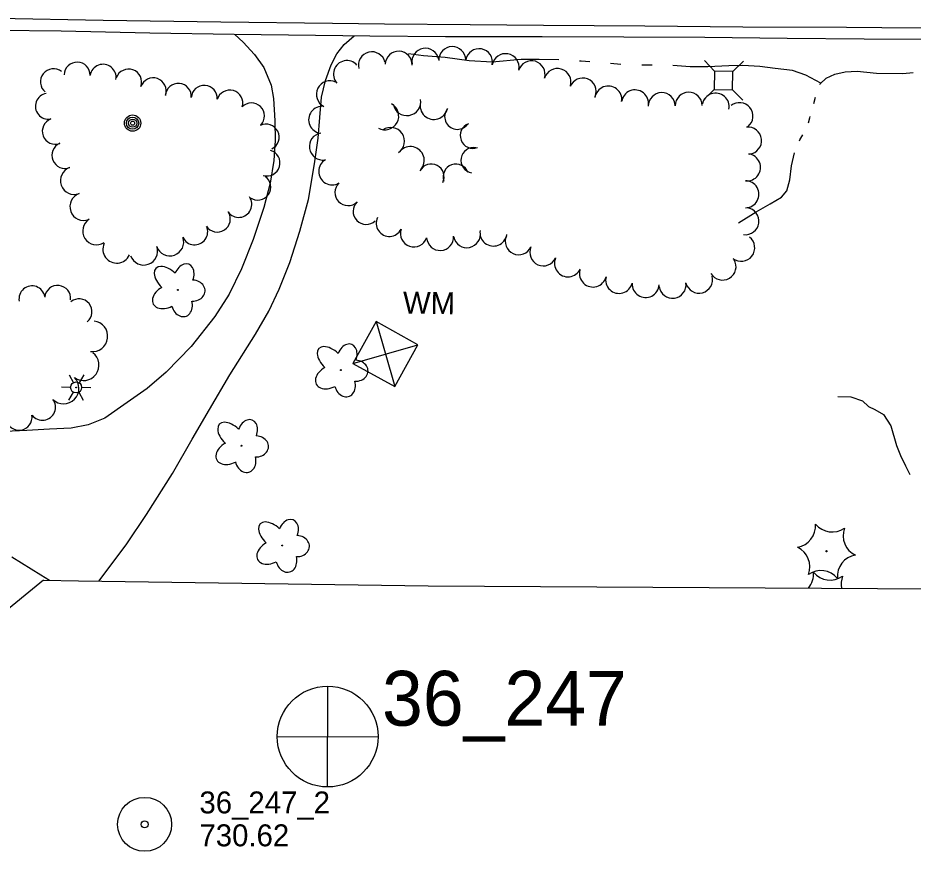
# Model space of a CAD drawing. Extents: x 589250 to 1188077, y 162953 to 363065.
# Drawn here: x 595184.3 to 595429, y 164804.2 to 165039.5 of the extents above; entities that cross this region are included whole.
import ezdxf

# ---------------------------------------------------------------- set-up
doc = ezdxf.new("R2010")
doc.units = 0
for name, color, linetype in [('E_DWY', 7, 'Continuous'), ('E_LAND_TreeLine_P', 7, 'Continuous'), ('E_LAND_Vegetation', 7, 'Continuous'), ('E_LTG', 7, 'Continuous'), ('E_MAP_Limits', 7, 'Continuous'), ('E_MAP_PassPoints', 7, 'Continuous'), ('E_MAP_PhotoCenter', 7, 'Continuous'), ('E_MISCPROP', 7, 'Continuous'), ('E_MISCPROP_Text', 7, 'Continuous'), ('E_RDWY', 7, 'Continuous'), ('E_RDWY_Gravel', 7, 'Continuous'), ('E_UTL_AG_Bold', 7, 'Continuous'), ('E_WTR_FlowLine', 7, 'Continuous')]:
    doc.layers.add(name, color=color, linetype=linetype)

msp = doc.modelspace()

# ---------------------------------------------------------------- linework, layer by layer
at = {"layer": 'E_DWY'}
for p, q in [((595243.55, 165034.97), (595245.91, 165032.85)), ((595273.48, 165032.24), (595276.24, 165034.58)), ((595245.91, 165032.85), (595248.96, 165029.47)), ((595271.46, 165029.69), (595273.48, 165032.24)), ((595248.96, 165029.47), (595251.49, 165025.92)), ((595269.9, 165026.66), (595271.46, 165029.69)), ((595268.35, 165022.42), (595269.9, 165026.66)), ((595251.49, 165025.92), (595253.49, 165021.14)), ((595267.32, 165017.84), (595268.35, 165022.42)), ((595253.49, 165021.14), (595254.14, 165017.47)), ((595254.14, 165017.47), (595254.48, 165011.4)), ((595266.82, 165012.31), (595267.32, 165017.84)), ((595266.37, 165006.61), (595266.82, 165012.31)), ((595254.48, 165011.4), (595254.61, 165005.98)), ((595265.41, 164999.58), (595266.37, 165006.61)), ((595254.61, 165005.98), (595254.26, 165000.53)), ((595254.26, 165000.53), (595253.22, 164994.31)), ((595263.71, 164989.87), (595265.41, 164999.58)), ((595253.22, 164994.31), (595251.5, 164987.65)), ((595261.38, 164981.19), (595263.71, 164989.87)), ((595251.5, 164987.65), (595248.57, 164978.86)), ((595258.66, 164972.59), (595261.38, 164981.19)), ((595248.57, 164978.86), (595245.38, 164970.86)), ((595255.72, 164965.32), (595258.66, 164972.59)), ((595245.38, 164970.86), (595242.08, 164963.92)), ((595252.85, 164959.25), (595255.72, 164965.32)), ((595242.08, 164963.92), (595238.12, 164957.87)), ((595238.12, 164957.87), (595231.65, 164949.65)), ((595249.24, 164953.02), (595252.85, 164959.25)), ((595242.22, 164941.88), (595249.24, 164953.02)), ((595231.65, 164949.65), (595224.78, 164942.6)), ((595224.78, 164942.6), (595219.58, 164938.18)), ((595236.62, 164932.42), (595242.22, 164941.88)), ((595219.58, 164938.18), (595214.11, 164934.29)), ((595214.11, 164934.29), (595208.04, 164930.06)), ((595231.91, 164924.26), (595236.62, 164932.42)), ((595208.04, 164930.06), (595203.47, 164928.22)), ((595186.73, 164926.61), (595176.03, 164926.17)), ((595192.91, 164926.98), (595186.73, 164926.61)), ((595198.8, 164927.26), (595192.91, 164926.98)), ((595203.47, 164928.22), (595198.8, 164927.26)), ((595226.51, 164914.91), (595231.91, 164924.26)), ((595219.42, 164903.69), (595226.51, 164914.91)), ((595214.06, 164895.62), (595219.42, 164903.69)), ((595206.5, 164885.48), (595214.06, 164895.62)), ((595182.63, 164892.06), (595190.56, 164887.17)), ((595190.56, 164887.17), (595192.95, 164885.7))]:
    msp.add_line(p, q, dxfattribs=at)
at = {"layer": 'E_LAND_TreeLine_P'}
for centre, radius, start, end in [((595295.69, 165027.53), 3.69, 9.7406, 189.7406), ((595303.04, 165027.98), 3.69, 1.1157, 181.1157), ((595281.05, 165026.55), 3.69, 13.4116, 193.4116), ((595288.39, 165026.7), 3.69, 358.0637, 178.0637), ((595310.36, 165027.38), 3.69, 349.5869, 169.5869), ((595317.61, 165026.04), 3.69, 349.5869, 169.5869), ((595200.48, 165023.85), 3.56, 358.3115, 178.3115), ((595207.56, 165023.27), 3.56, 350.8386, 170.8386), ((595274.24, 165024.14), 3.69, 41.8847, 221.8847), ((595324.72, 165024.1), 3.69, 343.3792, 163.3792), ((595193.99, 165022.04), 3.56, 51.426, 231.426), ((595214.54, 165021.95), 3.56, 340.4339, 160.4339), ((595331.8, 165021.99), 3.69, 343.3792, 163.3792), ((595221.25, 165019.56), 3.56, 340.2375, 160.2375), ((595228.14, 165018.03), 3.56, 355.3287, 175.3287), ((595269.56, 165018.6), 3.69, 63.4212, 243.4212), ((595338.69, 165019.37), 3.69, 338.5138, 158.5138), ((595192.62, 165015.36), 3.56, 99.7772, 279.7772), ((595235.24, 165017.5), 3.56, 356.6029, 176.6029), ((595242.2, 165016.22), 3.56, 343.8822, 163.8822), ((595345.7, 165017.19), 3.69, 351.7023, 171.7023), ((595353, 165016.13), 3.69, 351.7023, 171.7023), ((595360.32, 165015.38), 3.69, 0.8292, 180.8292), ((595367.7, 165015.49), 3.69, 0.8292, 180.8292), ((595375.04, 165015.26), 3.69, 348.7577, 168.7577), ((595290.63, 165016.57), 3.78, 189.8793, 9.8793), ((595248.13, 165012.68), 3.56, 316.0681, 136.0681), ((595267.46, 165011.64), 3.69, 83.4005, 263.4005), ((595284.62, 165012.66), 3.78, 241.6772, 61.6772), ((595298.02, 165015.53), 3.78, 167.0923, 347.0923), ((595304.44, 165012.52), 3.49, 141.5636, 321.5636), ((595381.58, 165012.65), 3.69, 309.0768, 129.0768), ((595194.51, 165008.53), 3.56, 110.6636, 290.6636), ((595252.14, 165006.91), 3.56, 296.6672, 116.6672), ((595286.18, 165005.77), 3.78, 304.4135, 124.4135), ((595308.7, 165007.31), 3.49, 110.7702, 290.7702), ((595383.92, 165005.95), 3.69, 276.6589, 96.6589), ((595267.66, 165004.33), 3.69, 99.0327, 279.0327), ((595197.12, 165001.91), 3.56, 112.2184, 292.2184), ((595291.61, 165000.54), 3.78, 317.9949, 137.9949), ((595252.37, 164999.83), 3.56, 253.8297, 73.8297), ((595308.9, 165000.57), 3.49, 80.0281, 260.0281), ((595383.64, 164998.62), 3.69, 263.292, 83.292), ((595270.2, 164997.54), 3.69, 120.2629, 300.2629), ((595297.31, 164996.06), 3.49, 332.8197, 152.8197), ((595304.04, 164996.03), 3.49, 19.5506, 199.5506), ((595199.68, 164995.02), 3.79, 110.0985, 290.0985), ((595249.85, 164993.25), 3.56, 234.9615, 54.9615), ((595383.21, 164991.27), 3.69, 270.417, 90.417), ((595274.54, 164991.77), 3.58, 133.8249, 313.8249), ((595202.29, 164987.9), 3.79, 110.0985, 290.0985), ((595244.67, 164988.51), 3.56, 215.3288, 35.3288), ((595279.49, 164986.61), 3.58, 133.8249, 313.8249), ((595383.2, 164983.9), 3.69, 262.1707, 82.1707), ((595238.79, 164984.5), 3.56, 212.8084, 32.8084), ((595285.83, 164983.32), 3.58, 153.5837, 333.5837), ((595205.79, 164981.23), 3.79, 122.4705, 302.4705), ((595232.61, 164980.99), 3.56, 204.821, 24.821), ((595292.54, 164980.55), 3.69, 161.4466, 341.4466), ((595299.72, 164979.59), 3.69, 183.2441, 3.2441), ((595307.04, 164980.34), 3.69, 191.7269, 11.7269), ((595314.29, 164980.79), 3.69, 171.3267, 351.3267), ((595321.2, 164978.4), 3.69, 155.3334, 335.3334), ((595211.31, 164976.22), 3.79, 155.7934, 335.7934), ((595225.82, 164978.21), 3.79, 199.3254, 19.3254), ((595382.06, 164976.64), 3.69, 232.1268, 52.1268), ((595218.67, 164975.7), 3.79, 199.3254, 19.3254), ((595327.93, 164975.37), 3.69, 155.8498, 335.8498), ((595334.67, 164972.37), 3.69, 156.0176, 336.0176), ((595376.94, 164971.49), 3.69, 210.3307, 30.3307), ((595341.49, 164969.59), 3.69, 166.2594, 346.2594), ((595348.66, 164967.84), 3.69, 166.2594, 346.2594), ((595370.51, 164967.91), 3.69, 194.8378, 14.8378), ((595188.12, 164962.66), 3.55, 10, 190), ((595195.14, 164962.79), 3.55, 353.9177, 173.9177), ((595355.92, 164966.72), 3.69, 176.5602, 356.5602), ((595363.28, 164966.52), 3.69, 187.542, 7.542), ((595200.99, 164959.12), 3.55, 309.3285, 129.3285), ((595204.62, 164952.41), 4.21, 263.0906, 83.0906), ((595202.24, 164944.52), 4.21, 233.7609, 53.7609), ((595196.76, 164938.16), 4.21, 225.416, 45.416), ((595190.99, 164933.01), 3.55, 217.5212, 37.5212), ((595184.59, 164930.28), 3.55, 188.7829, 8.7829)]:
    msp.add_arc(centre, radius, start, end, dxfattribs=at)
at = {"layer": 'E_LAND_Vegetation'}
for centre, radius in [((595228.02, 164965.09), 0.128), ((595272.58, 164943.17), 0.128), ((595245.37, 164922.47), 0.128), ((595256.55, 164895.19), 0.128), ((595405.37, 164893.61), 0.167)]:
    msp.add_circle(centre, radius, dxfattribs=at)
for centre, radius, start, end in [((595396.46, 164900.54), 5.91, 279.2862, 4.9623), ((595406.91, 164904.78), 5.9, 219.2465, 305.0114), ((595415.81, 164897.86), 5.9, 159.2465, 245.0114), ((595394.92, 164889.36), 5.9, 339.2465, 65.0114), ((595414.23, 164886.74), 5.9, 99.2418, 185.0068), ((595403.82, 164882.44), 5.9, 39.2465, 125.0114), ((595395.91, 164887.35), 5.91, 320.1017, 4.9623), ((595406.37, 164891.6), 5.9, 219.2465, 305.0114), ((595415.27, 164884.67), 5.9, 159.2465, 191.3555)]:
    msp.add_arc(centre, radius, start, end, dxfattribs=at)
for centre, major_axis, ratio in [((595229.69, 164968.74), (-1.32, -3.38), 0.716896), ((595225.45, 164967.73), (3.45, -3.27), 0.560249), ((595232, 164964.92), (-3.45, 0.14), 0.832022), ((595225.02, 164963.23), (3.72, 1.99), 0.691916), ((595229.13, 164961.35), (-0.89, 3.5), 0.782863), ((595274.26, 164946.81), (-1.32, -3.38), 0.716896), ((595270.02, 164945.8), (3.45, -3.27), 0.560249), ((595276.56, 164942.99), (-3.45, 0.14), 0.832022), ((595269.58, 164941.3), (3.72, 1.99), 0.691916), ((595273.7, 164939.42), (-0.89, 3.5), 0.782863), ((595242.8, 164925.11), (3.45, -3.27), 0.560249), ((595247.05, 164926.11), (-1.32, -3.38), 0.716896), ((595249.35, 164922.29), (-3.45, 0.14), 0.832022), ((595242.37, 164920.6), (3.72, 1.99), 0.691916), ((595246.49, 164918.73), (-0.89, 3.5), 0.782863), ((595253.99, 164897.82), (3.45, -3.27), 0.560249), ((595258.23, 164898.83), (-1.32, -3.38), 0.716896), ((595260.53, 164895.01), (-3.45, 0.14), 0.832022), ((595253.55, 164893.32), (3.72, 1.99), 0.691916), ((595257.67, 164891.44), (-0.89, 3.5), 0.782863)]:
    msp.add_ellipse(centre, major_axis=major_axis, ratio=ratio, start_param=1.570796, end_param=4.712389, dxfattribs=at)
at = {"layer": 'E_LTG'}
for p, q in [((595198.26, 164941.91), (595199.48, 164939.73)), ((595202.26, 164941.85), (595200.98, 164939.7)), ((595198.7, 164938.44), (595196.2, 164938.48)), ((595204.2, 164938.35), (595201.7, 164938.39)), ((595199.43, 164937.13), (595198.15, 164934.99)), ((595200.93, 164937.1), (595202.14, 164934.92))]:
    msp.add_line(p, q, dxfattribs=at)
for radius in [1.5, 0.125]:
    msp.add_circle((595200.2, 164938.42), radius, dxfattribs=at)
at = {"layer": 'E_MAP_Limits'}
for p, q in [((595191.23, 164885.74), (595092.3, 164804.2)), ((595191.23, 164885.74), (595200.81, 164885.56)), ((595200.81, 164885.56), (595296.48, 164884.2)), ((595296.48, 164884.2), (595479.15, 164883.09))]:
    msp.add_line(p, q, dxfattribs=at)
at = {"layer": 'E_MAP_PassPoints'}
for radius in [7.38, 7.38, 0.945, 0.945]:
    msp.add_circle((595218.91, 164818.91), radius, dxfattribs=at)
at = {"layer": 'E_MAP_PhotoCenter'}
for p, q in [((595268.92, 164856.71), (595268.86, 164829.3)), ((595268.92, 164856.71), (595268.86, 164829.3)), ((595255.23, 164842.91), (595282.69, 164842.89)), ((595255.23, 164842.91), (595282.69, 164842.89))]:
    msp.add_line(p, q, dxfattribs=at)
msp.add_circle((595268.97, 164842.91), 13.78, dxfattribs=at)
msp.add_circle((595268.97, 164842.91), 13.78, dxfattribs=at)
at = {"layer": 'E_MISCPROP'}
for p, q in [((595282.21, 164956.45), (595275.89, 164944.99)), ((595282.21, 164956.45), (595287.34, 164938.67)), ((595293.67, 164950.12), (595282.21, 164956.45)), ((595275.89, 164944.99), (595293.67, 164950.12)), ((595287.34, 164938.67), (595293.67, 164950.12)), ((595275.89, 164944.99), (595287.34, 164938.67))]:
    msp.add_line(p, q, dxfattribs=at)
for radius in [2.23, 1.67, 1.12, 0.558]:
    msp.add_circle((595215.64, 165010.73), radius, dxfattribs=at)
at = {"layer": 'E_RDWY'}
for p, q in [((595174.81, 165039.52), (595207.61, 165038.94)), ((595207.61, 165038.94), (595239.72, 165038.47)), ((595239.72, 165038.47), (595270.32, 165038.09)), ((595270.32, 165038.09), (595284.53, 165037.92)), ((595284.53, 165037.92), (595307.91, 165037.68)), ((595307.91, 165037.68), (595327.98, 165037.53)), ((595327.98, 165037.53), (595355.71, 165037.35)), ((595355.71, 165037.35), (595382.49, 165037.11)), ((595382.49, 165037.11), (595410.79, 165036.96)), ((595410.79, 165036.96), (595420.49, 165036.87)), ((595420.49, 165036.87), (595448.68, 165036.74))]:
    msp.add_line(p, q, dxfattribs=at)
at = {"layer": 'E_RDWY_Gravel'}
for p, q in [((595196.08, 165035.91), (595171.59, 165036.19)), ((595220.32, 165035.32), (595196.08, 165035.91)), ((595243.37, 165034.97), (595220.32, 165035.32)), ((595280.52, 165034.53), (595243.37, 165034.97)), ((595301.2, 165034.36), (595280.52, 165034.53)), ((595327.62, 165034.3), (595301.2, 165034.36)), ((595349.93, 165034.22), (595327.62, 165034.3)), ((595372.1, 165034.11), (595349.93, 165034.22)), ((595394.57, 165033.89), (595372.1, 165034.11)), ((595415.66, 165033.72), (595394.57, 165033.89)), ((595435.08, 165033.64), (595415.66, 165033.72))]:
    msp.add_line(p, q, dxfattribs=at)
at = {"layer": 'E_UTL_AG_Bold'}
for p, q in [((595374.77, 165024.96), (595371.99, 165027.84)), ((595379.77, 165024.88), (595382.64, 165027.66)), ((595374.77, 165024.96), (595374.69, 165019.96)), ((595379.77, 165024.88), (595374.77, 165024.96)), ((595379.68, 165019.88), (595379.77, 165024.88)), ((595374.69, 165019.96), (595371.81, 165017.18)), ((595374.69, 165019.96), (595379.68, 165019.88)), ((595379.68, 165019.88), (595382.47, 165017))]:
    msp.add_line(p, q, dxfattribs=at)
at = {"layer": 'E_WTR_FlowLine'}
for p, q in [((595295.17, 165029.11), (595291.03, 165029.65)), ((595301.11, 165028.66), (595295.17, 165029.11)), ((595307.68, 165027.76), (595301.11, 165028.66)), ((595313.98, 165027.42), (595307.68, 165027.76)), ((595321.9, 165028.13), (595313.98, 165027.42)), ((595326.8, 165028.17), (595321.9, 165028.13)), ((595332.14, 165028), (595326.8, 165028.17)), ((595338.25, 165027.68), (595337.81, 165027.7)), ((595340.65, 165027.46), (595338.25, 165027.68)), ((595349.16, 165026.81), (595346.32, 165027)), ((595357.7, 165026.61), (595354.85, 165026.56)), ((595368.06, 165026.13), (595363.39, 165026.52)), ((595378.68, 165026.37), (595372.93, 165026.14)), ((595382.49, 165026.48), (595378.68, 165026.37)), ((595387.12, 165026.19), (595382.49, 165026.48)), ((595391.29, 165025.7), (595387.12, 165026.19)), ((595372.93, 165026.14), (595368.06, 165026.13)), ((595396.04, 165025.13), (595391.29, 165025.7)), ((595399.69, 165023.88), (595396.04, 165025.13)), ((595403.83, 165021.68), (595399.69, 165023.88)), ((595405.25, 165023), (595407.61, 165024.13)), ((595407.61, 165024.13), (595410.49, 165024.72)), ((595410.49, 165024.72), (595413.71, 165024.91)), ((595413.71, 165024.91), (595419.05, 165024.43)), ((595419.05, 165024.43), (595426.21, 165024.35)), ((595426.21, 165024.35), (595429.04, 165024.54)), ((595403.57, 165021.31), (595403.65, 165021.51)), ((595403.65, 165021.51), (595405.25, 165023)), ((595401.93, 165016.08), (595402.36, 165017.86)), ((595400.41, 165010.81), (595400.83, 165012.2)), ((595400.83, 165012.2), (595400.94, 165012.56)), ((595398.07, 165006.14), (595398.88, 165007.51)), ((595397.97, 165005.92), (595398.07, 165006.14)), ((595395.78, 164999.01), (595396.57, 165002.56)), ((595395.35, 164995.2), (595395.78, 164999.01)), ((595394.5, 164992.25), (595395.35, 164995.2)), ((595393.06, 164990.47), (595394.5, 164992.25)), ((595390, 164988.65), (595393.06, 164990.47)), ((595386.09, 164986.47), (595390, 164988.65)), ((595381.26, 164983.49), (595386.09, 164986.47)), ((595408.44, 164935.98), (595412.01, 164935.9)), ((595412.01, 164935.9), (595415.18, 164934.75)), ((595415.18, 164934.75), (595416.88, 164933.23)), ((595416.88, 164933.23), (595418.57, 164932.43)), ((595418.57, 164932.43), (595420.93, 164931.06)), ((595420.93, 164931.06), (595422.94, 164927.89)), ((595422.94, 164927.89), (595424.47, 164922.56)), ((595424.47, 164922.56), (595425.56, 164919.79)), ((595425.56, 164919.79), (595426.97, 164916.96)), ((595426.97, 164916.96), (595428.15, 164914.57))]:
    msp.add_line(p, q, dxfattribs=at)

# ---------------------------------------------------------------- texts
at = {"layer": 'E_MAP_PassPoints'}
for s, p in [('36_247_2', (595233.91, 164821.9)), ('36_247_2', (595233.91, 164821.9)), ('730.62', (595233.91, 164812.9)), ('730.62', (595233.91, 164812.9))]:
    msp.add_text(s, height=6, dxfattribs=at).set_placement(p)
at = {"layer": 'E_MAP_PhotoCenter'}
msp.add_text('36_247', height=15, dxfattribs=at).set_placement((595283.83, 164845.89))
msp.add_text('36_247', height=15, dxfattribs=at).set_placement((595283.83, 164845.89))
at = {"layer": 'E_MISCPROP_Text'}
msp.add_text('WM', height=6, rotation=359.0351, dxfattribs=at).set_placement((595289.5, 164958.66))

doc.saveas('drawing.dxf')
